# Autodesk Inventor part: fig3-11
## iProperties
Created: 2005-02
Part Number: fig3-11
Document SubType Name: Modeling
Designer: CADCIM
Manufacturer: Standard
Standards Organization: Custom
Author: CADCIM
